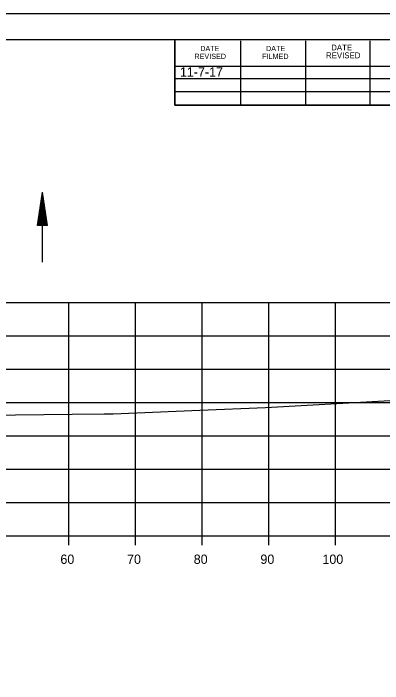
# Model space of a CAD drawing. Extents: x 1374311 to 1383814, y 384102 to 406278.
# Drawn here: x 1381680.4 to 1381735.7, y 389344.2 to 389444.7 of the extents above; entities that cross this region are included whole.
import ezdxf

# ---------------------------------------------------------------- set-up
doc = ezdxf.new("R2010")
doc.units = 0
for name, color, linetype in [('R_Axis', 7, 'Continuous'), ('R_Axis Annot', 7, 'Continuous'), ('R_Border', 7, 'Continuous'), ('R_Draft', 7, 'Continuous'), ('R_Exist Surface', 7, 'Continuous'), ('R_Fin Surface', 7, 'Continuous'), ('R_Grid', 7, 'Continuous'), ('R_No Plot', 7, 'Continuous'), ('R_Water', 7, 'Continuous')]:
    doc.layers.add(name, color=color, linetype=linetype)

msp = doc.modelspace()

# ---------------------------------------------------------------- linework, layer by layer
at = {"layer": 'R_Axis'}
for p, q in [((1381488.66, 389366.36), (1381768.66, 389366.36)), ((1381688.66, 389364.96), (1381688.66, 389366.36)), ((1381698.66, 389364.96), (1381698.66, 389366.36)), ((1381708.66, 389364.96), (1381708.66, 389366.36)), ((1381718.66, 389364.96), (1381718.66, 389366.36)), ((1381728.66, 389364.96), (1381728.66, 389366.36))]:
    msp.add_line(p, q, dxfattribs=at)
at = {"layer": 'R_Border'}
for p, q in [((1381470.66, 389440.82), (1381786.84, 389440.82)), ((1381704.58, 389430.94), (1381704.58, 389440.82)), ((1381714.44, 389430.94), (1381714.44, 389440.62)), ((1381724.2, 389430.94), (1381724.2, 389440.62)), ((1381733.88, 389430.94), (1381733.88, 389440.62)), ((1381704.58, 389436.8), (1381743.74, 389436.8)), ((1381704.58, 389434.94), (1381743.74, 389434.94)), ((1381704.58, 389430.94), (1381704.58, 389433)), ((1381704.58, 389433), (1381743.74, 389433)), ((1381786.84, 389430.94), (1381704.58, 389430.94))]:
    msp.add_line(p, q, dxfattribs=at)
at = {"layer": 'R_Draft'}
for p, q in [((1381683.96, 389412.9), (1381684.71, 389417.9)), ((1381684.08, 389412.9), (1381684.71, 389417.07)), ((1381685.46, 389412.9), (1381684.71, 389417.9)), ((1381685.33, 389412.9), (1381684.71, 389417.07)), ((1381684.21, 389412.9), (1381684.71, 389416.21)), ((1381685.2, 389412.9), (1381684.71, 389416.21)), ((1381684.33, 389412.9), (1381684.71, 389415.38)), ((1381685.08, 389412.9), (1381684.71, 389415.38)), ((1381684.46, 389412.9), (1381684.71, 389414.53)), ((1381684.95, 389412.9), (1381684.71, 389414.53)), ((1381684.59, 389412.9), (1381684.71, 389413.69)), ((1381684.82, 389412.9), (1381684.71, 389413.69)), ((1381685.46, 389412.9), (1381683.96, 389412.9))]:
    msp.add_line(p, q, dxfattribs=at)
at = {"layer": 'R_Exist Surface'}
msp.add_lwpolyline([(1381663.64, 389384.32), (1381689.16, 389384.59), (1381693.98, 389384.68), (1381695.34, 389384.64), (1381708.33, 389385.22), (1381718.15, 389385.61), (1381729.77, 389386.24), (1381737.7, 389386.71), (1381743.75, 389386.18), (1381747.77, 389385.89), (1381751.87, 389386.24), (1381758.18, 389386.89), (1381766.54, 389387), (1381768.66, 389387.09)], dxfattribs=at)
at = {"layer": 'R_Grid'}
for p, q in [((1381488.66, 389401.36), (1381768.66, 389401.36)), ((1381688.66, 389366.36), (1381688.66, 389401.36)), ((1381698.66, 389366.36), (1381698.66, 389401.36)), ((1381708.66, 389366.36), (1381708.66, 389401.36)), ((1381718.66, 389366.36), (1381718.66, 389401.36)), ((1381728.66, 389366.36), (1381728.66, 389401.36)), ((1381488.66, 389396.36), (1381768.66, 389396.36)), ((1381488.66, 389391.36), (1381768.66, 389391.36)), ((1381488.66, 389386.36), (1381768.66, 389386.36)), ((1381488.66, 389381.36), (1381768.66, 389381.36)), ((1381488.66, 389376.36), (1381768.66, 389376.36)), ((1381488.66, 389371.36), (1381768.66, 389371.36)), ((1381488.66, 389366.36), (1381768.66, 389366.36))]:
    msp.add_line(p, q, dxfattribs=at)
at = {"layer": 'R_No Plot'}
msp.add_line((1381458.26, 389444.71), (1381791.59, 389444.71), dxfattribs=at)
for points in [[(1381458.25, 389444.71), (1381791.59, 389444.71), (1381791.59, 389231.37), (1381458.25, 389231.37)], [(1381704.58, 389440.82), (1381704.58, 389430.94), (1381740.31, 389430.94), (1381740.31, 389428.02), (1381763.51, 389428.02), (1381763.51, 389404.8), (1381786.84, 389404.8), (1381786.84, 389235.36), (1381470.66, 389235.36), (1381470.66, 389440.82)]]:
    msp.add_lwpolyline(points, close=True, dxfattribs=at)
at = {"layer": 'R_Water'}
msp.add_line((1381684.71, 389407.4), (1381684.71, 389417.9), dxfattribs=at)

# ---------------------------------------------------------------- texts
at = {"layer": 'R_Axis Annot'}
for s, p in [('60', (1381687.4, 389362.16)), ('70', (1381697.4, 389362.16)), ('80', (1381707.4, 389362.16)), ('90', (1381717.4, 389362.16)), ('100', (1381726.7, 389362.16))]:
    msp.add_text(s, height=1.4, dxfattribs=at).set_placement(p)
at = {"layer": 'R_Border'}
for s, height, p in [('DATE', 0.782, (1381708.38, 389439.06)), ('DATE', 0.782, (1381718.24, 389439.06)), ('DATE', 0.879, (1381728.02, 389439.16)), ('REVISED', 0.782, (1381707.5, 389437.88)), ('FILMED', 0.782, (1381717.66, 389437.88)), ('REVISED', 0.879, (1381727.24, 389437.98))]:
    msp.add_text(s, height=height, rotation=360, dxfattribs=at).set_placement(p)
at = {"layer": 'R_Fin Surface'}
msp.add_text('11-7-17', height=1.4, dxfattribs=at).set_placement((1381705.33, 389435.23))

doc.saveas('drawing.dxf')
